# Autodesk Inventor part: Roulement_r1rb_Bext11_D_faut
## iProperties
Created: 2011-10
Part Number: Roulement_r1rb_Bext11_D_faut
Document SubType Name: Modeling
Designer: Bruno
Author: Bruno
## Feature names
1. Base1
